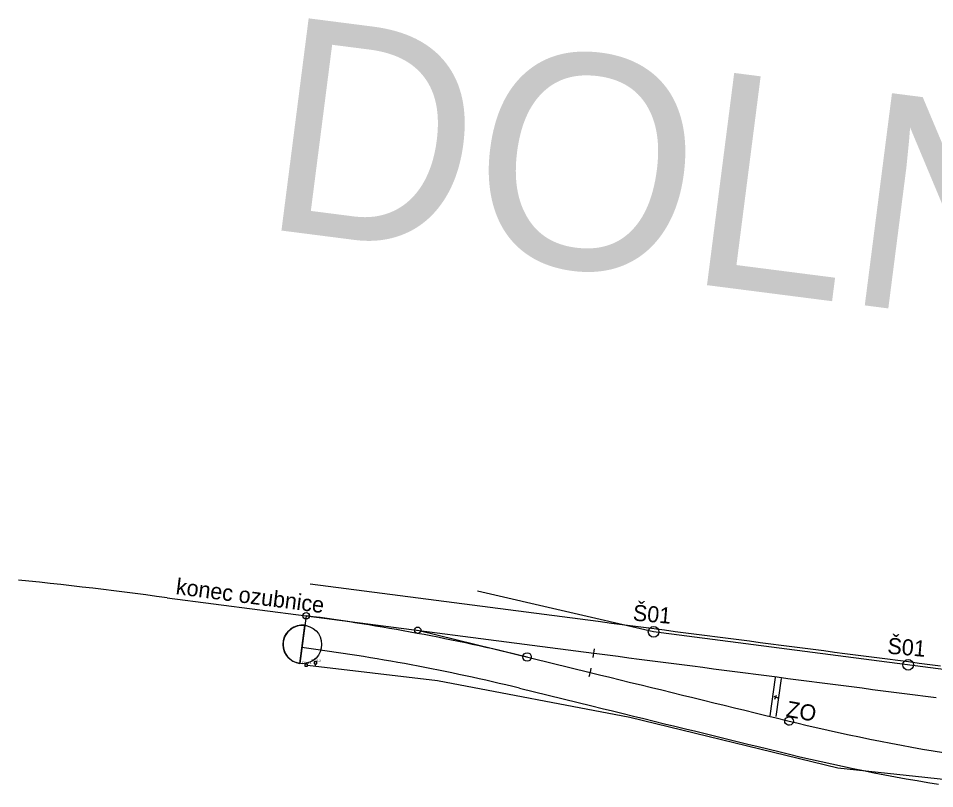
# Model space of a CAD drawing. Extents: x -669661 to -669105, y -977202 to -977030.
# Drawn here: x -669181.271 to -669176.987, y -977097.733 to -977094.133 of the extents above; entities that cross this region are included whole.
import ezdxf

# ---------------------------------------------------------------- set-up
doc = ezdxf.new("R2010")
doc.units = 0
doc.layers.add('KOL_námezníky', color=7, linetype='Continuous')
doc.layers.add('Schéma', color=7, linetype='Continuous')

# ---------------------------------------------------------------- blocks, each defined once
blk = doc.blocks.new('Z3.50')
at = {"layer": 'KOL_námezníky'}
for p, q in [((-27.7, 181.3), (-26.5, -174.8)), ((33.2, -174.7), (31.9, 181.4))]:
    blk.add_line(p, q, dxfattribs=at)

msp = doc.modelspace()

# ---------------------------------------------------------------- linework, layer by layer
at = {"layer": 'Schéma'}
for p, q in [((-669179.9065, -977096.7765), (-669178.5609, -977096.9512)), ((-669180.5762, -977096.8408), (-669179.9259, -977096.9252)), ((-669179.9259, -977096.9252), (-669179.9548, -977097.1484)), ((-669179.9259, -977096.9252), (-669178.5802, -977097.1)), ((-669179.4041, -977096.993), (-669178.5971, -977097.1903)), ((-669178.5802, -977097.1), (-669178.5664, -977097.1018)), ((-669178.5664, -977097.1018), (-669178.5168, -977097.1082)), ((-669178.5168, -977097.1082), (-669178.4672, -977097.1146)), ((-669179.9319, -977097.1512), (-669179.9324, -977097.1603)), ((-669179.9194, -977097.1519), (-669179.9319, -977097.1512)), ((-669179.9199, -977097.161), (-669179.9194, -977097.1519)), ((-669179.9198, -977097.1561), (-669179.3122, -977097.2285)), ((-669179.8883, -977097.1402), (-669179.8888, -977097.1493)), ((-669179.8888, -977097.1493), (-669179.8763, -977097.15)), ((-669179.8758, -977097.1408), (-669179.8883, -977097.1402)), ((-669179.8827, -977097.1498), (-669179.8842, -977097.1595)), ((-669179.8763, -977097.15), (-669179.8758, -977097.1408)), ((-669178.4672, -977097.1146), (-669178.4176, -977097.1211)), ((-669178.4176, -977097.1211), (-669178.368, -977097.1275)), ((-669178.368, -977097.1275), (-669178.3185, -977097.134)), ((-669178.3185, -977097.134), (-669178.2689, -977097.1404)), ((-669178.2689, -977097.1404), (-669178.2193, -977097.1468)), ((-669178.2193, -977097.1468), (-669178.1697, -977097.1533)), ((-669178.1697, -977097.1533), (-669178.1201, -977097.1597)), ((-669179.9324, -977097.1603), (-669179.9199, -977097.161)), ((-669178.5971, -977097.1903), (-669178.5542, -977097.2008)), ((-669178.1201, -977097.1597), (-669178.0705, -977097.1661)), ((-669178.0705, -977097.1661), (-669178.021, -977097.1726)), ((-669178.021, -977097.1726), (-669177.9714, -977097.179)), ((-669177.9714, -977097.179), (-669177.9218, -977097.1855)), ((-669177.9218, -977097.1855), (-669177.8722, -977097.1919)), ((-669177.8722, -977097.1919), (-669177.8226, -977097.1983)), ((-669177.8226, -977097.1983), (-669177.773, -977097.2048)), ((-669179.3122, -977097.2285), (-669178.4119, -977097.3996)), ((-669178.5542, -977097.2008), (-669178.5056, -977097.2126)), ((-669178.5056, -977097.2126), (-669178.4571, -977097.2245)), ((-669178.4571, -977097.2245), (-669178.4085, -977097.2364)), ((-669178.4085, -977097.2364), (-669178.3599, -977097.2483)), ((-669177.773, -977097.2048), (-669177.7235, -977097.2112)), ((-669177.7235, -977097.2112), (-669177.6739, -977097.2177)), ((-669177.6739, -977097.2177), (-669177.6243, -977097.2241)), ((-669177.6243, -977097.2241), (-669177.5747, -977097.2305)), ((-669177.5747, -977097.2305), (-669177.5251, -977097.237)), ((-669177.5251, -977097.237), (-669177.4755, -977097.2434)), ((-669178.9286, -977097.2636), (-669178.5898, -977097.3465)), ((-669178.3599, -977097.2483), (-669178.3114, -977097.2601)), ((-669178.3114, -977097.2601), (-669178.2628, -977097.272)), ((-669178.2628, -977097.272), (-669178.2142, -977097.2839)), ((-669178.2142, -977097.2839), (-669178.1656, -977097.2958)), ((-669177.4755, -977097.2434), (-669177.4259, -977097.2498)), ((-669177.4259, -977097.2498), (-669177.3764, -977097.2563)), ((-669177.3764, -977097.2563), (-669177.3268, -977097.2627)), ((-669177.3268, -977097.2627), (-669177.2772, -977097.2692)), ((-669177.2772, -977097.2692), (-669177.2276, -977097.2756)), ((-669177.2276, -977097.2756), (-669177.178, -977097.282)), ((-669177.178, -977097.282), (-669177.1284, -977097.2885)), ((-669178.1656, -977097.2958), (-669178.1171, -977097.3076)), ((-669178.1171, -977097.3076), (-669178.0685, -977097.3195)), ((-669178.0685, -977097.3195), (-669178.0199, -977097.3314)), ((-669177.7395, -977097.3016), (-669177.7209, -977097.3091)), ((-669177.734, -977097.3147), (-669177.7266, -977097.296)), ((-669177.1284, -977097.2885), (-669177.0789, -977097.2949)), ((-669177.0789, -977097.2949), (-669177.0293, -977097.3014)), ((-669177.0293, -977097.3014), (-669176.9797, -977097.3078)), ((-669178.5898, -977097.3465), (-669178.5413, -977097.3584)), ((-669178.5413, -977097.3584), (-669178.4927, -977097.3702)), ((-669178.4927, -977097.3702), (-669178.4441, -977097.3821)), ((-669178.0199, -977097.3314), (-669177.9714, -977097.3433)), ((-669177.9714, -977097.3433), (-669177.9228, -977097.3551)), ((-669177.9228, -977097.3551), (-669177.8742, -977097.367)), ((-669177.8742, -977097.367), (-669177.8257, -977097.3789)), ((-669178.4441, -977097.3821), (-669178.3955, -977097.394)), ((-669178.4119, -977097.3996), (-669177.4407, -977097.6364)), ((-669178.3955, -977097.394), (-669178.347, -977097.4059)), ((-669178.347, -977097.4059), (-669178.2498, -977097.4296)), ((-669177.8257, -977097.3789), (-669177.7771, -977097.3908)), ((-669177.7771, -977097.3908), (-669177.7285, -977097.4026)), ((-669177.7285, -977097.4026), (-669177.6799, -977097.4145)), ((-669178.2498, -977097.4296), (-669178.2013, -977097.4415)), ((-669178.2013, -977097.4415), (-669178.1527, -977097.4534)), ((-669178.1527, -977097.4534), (-669178.1041, -977097.4652)), ((-669177.6799, -977097.4145), (-669177.6677, -977097.4175)), ((-669177.6677, -977097.4175), (-669177.6314, -977097.4263)), ((-669177.6314, -977097.4263), (-669177.5827, -977097.4379)), ((-669177.5827, -977097.4379), (-669177.534, -977097.4492)), ((-669177.534, -977097.4492), (-669177.4852, -977097.4602)), ((-669178.1041, -977097.4652), (-669177.8613, -977097.5246)), ((-669177.4852, -977097.4602), (-669177.4364, -977097.471)), ((-669177.4364, -977097.471), (-669177.3875, -977097.4815)), ((-669177.3875, -977097.4815), (-669177.3386, -977097.4918)), ((-669177.3386, -977097.4918), (-669177.2896, -977097.5018)), ((-669177.8613, -977097.5246), (-669177.8127, -977097.5365)), ((-669177.8127, -977097.5365), (-669177.7156, -977097.5602)), ((-669177.2896, -977097.5018), (-669177.2406, -977097.5116)), ((-669177.2406, -977097.5116), (-669177.1915, -977097.5211)), ((-669177.1915, -977097.5211), (-669177.1424, -977097.5303)), ((-669177.1424, -977097.5303), (-669177.0932, -977097.5393)), ((-669177.0932, -977097.5393), (-669177.0439, -977097.548)), ((-669177.7156, -977097.5602), (-669177.7032, -977097.5632)), ((-669177.7032, -977097.5632), (-669177.6664, -977097.5722)), ((-669177.6664, -977097.5722), (-669177.617, -977097.5839)), ((-669177.617, -977097.5839), (-669177.5675, -977097.5954)), ((-669177.0439, -977097.548), (-669176.9947, -977097.5565)), ((-669176.9947, -977097.5565), (-669176.9453, -977097.5647)), ((-669177.5675, -977097.5954), (-669177.518, -977097.6066)), ((-669177.518, -977097.6066), (-669177.4684, -977097.6176)), ((-669177.4684, -977097.6176), (-669177.4187, -977097.6282)), ((-669177.4407, -977097.6364), (-669176.533, -977097.7333)), ((-669177.4187, -977097.6282), (-669177.369, -977097.6387)), ((-669177.369, -977097.6387), (-669177.3193, -977097.6489)), ((-669177.3193, -977097.6489), (-669177.2695, -977097.6588)), ((-669177.2695, -977097.6588), (-669177.2196, -977097.6684)), ((-669177.2196, -977097.6684), (-669177.1697, -977097.6778)), ((-669177.1697, -977097.6778), (-669177.1197, -977097.6869)), ((-669177.1197, -977097.6869), (-669177.0697, -977097.6958)), ((-669177.0697, -977097.6958), (-669177.0197, -977097.7044)), ((-669177.0197, -977097.7044), (-669176.9695, -977097.7127))]:
    msp.add_line(p, q, dxfattribs=at)
for points in [[(-669180.5762, -977096.8408), (-669180.6258, -977096.8344), (-669180.6754, -977096.8279), (-669180.725, -977096.8216), (-669180.7746, -977096.8152), (-669180.8242, -977096.809), (-669180.8738, -977096.8028), (-669180.9234, -977096.7967), (-669180.9731, -977096.7908), (-669181.0227, -977096.785), (-669181.0724, -977096.7793), (-669181.1221, -977096.7739), (-669181.1718, -977096.7686), (-669181.2216, -977096.7636), (-669181.2713, -977096.7587)], [(-669175.4004, -977097.3767), (-669178.3011, -977097.0001), (-669179.1249, -977096.8105)], [(-669179.9548, -977097.1484), (-669179.9317, -977096.9699), (-669179.9317, -977096.9699)], [(-669178.5609, -977096.9512), (-669178.4975, -977096.9595), (-669178.4479, -977096.9659), (-669178.3983, -977096.9723), (-669178.3487, -977096.9788), (-669178.2496, -977096.9916), (-669178.2, -977096.9981), (-669178.1504, -977097.0045), (-669178.1008, -977097.011), (-669177.9521, -977097.0303), (-669177.9025, -977097.0367), (-669177.8529, -977097.0431), (-669177.8033, -977097.0496), (-669177.6546, -977097.0689), (-669177.605, -977097.0753), (-669177.5554, -977097.0818), (-669177.5058, -977097.0882), (-669177.4562, -977097.0947), (-669177.4066, -977097.1011), (-669177.357, -977097.1075), (-669177.3075, -977097.114), (-669177.2579, -977097.1204), (-669177.2083, -977097.1268), (-669177.1587, -977097.1333), (-669177.1091, -977097.1397), (-669177.0595, -977097.1462), (-669176.9604, -977097.159)], [(-669177.6725, -977097.4369), (-669177.6786, -977097.4341), (-669177.6842, -977097.4286), (-669177.6871, -977097.4237), (-669177.6881, -977097.4166), (-669177.6862, -977097.4089), (-669177.6824, -977097.4043), (-669177.6772, -977097.4001), (-669177.6698, -977097.3978), (-669177.663, -977097.3981), (-669177.6568, -977097.401), (-669177.6513, -977097.4064), (-669177.6484, -977097.4113), (-669177.6474, -977097.4184), (-669177.6493, -977097.4261), (-669177.6531, -977097.4307), (-669177.6583, -977097.4349), (-669177.6657, -977097.4372), (-669177.6725, -977097.4369)]]:
    msp.add_lwpolyline(points, dxfattribs=at)
for centre, radius in [((-669179.9259, -977096.9252), 0.015), ((-669179.9432, -977097.0591), 0.09), ((-669179.4041, -977096.993), 0.015), ((-669178.3011, -977097.0001), 0.025), ((-669178.893, -977097.1179), 0.02), ((-669177.1111, -977097.1546), 0.025)]:
    msp.add_circle(centre, radius, dxfattribs=at)
for centre, radius, start, end in [((-669181.1491, -977106.3462), 9.5, 76.2617, 82.60174), ((-669179.9432, -977097.0591), 0.09, 82.6032, 262.6017), ((-669181.1491, -977106.3462), 9.35, 76.26134, 82.60174), ((-669179.4041, -977096.993), 0.8308, 351.2224, 353.9811), ((-669179.4041, -977096.993), 0.8308, 344.8822, 347.6409)]:
    msp.add_arc(centre, radius, start, end, dxfattribs=at)

# ---------------------------------------------------------------- block references
at = {"layer": 'Schéma', "xscale": 0.0005052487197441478, "yscale": 0.0005052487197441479, "rotation": -8.028577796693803}
msp.add_blockref('Z3.50', (-669177.7318, -977097.3066), dxfattribs=at)

# ---------------------------------------------------------------- texts
at = {"layer": 'Schéma'}
for s, height, rotation, p in [('DOLNÍ POLUBNÝ', 1, 352.6919, (-669180.15, -977095.1109)), ('konec ozubnice', 0.075, 352.6118, (-669180.5377, -977096.8236)), ('Š01', 0.075, 354.9976, (-669178.4003, -977096.9474)), ('Š01', 0.075, 354.9976, (-669177.2103, -977097.1019)), ('EOV1.1', 0.009, 357.0527, (-669179.9447, -977097.1486)), ('EOV1.2', 0.009, 357.0527, (-669179.9011, -977097.1376)), ('ZO', 0.075, 349.8596, (-669177.6853, -977097.396))]:
    msp.add_text(s, height=height, rotation=rotation, dxfattribs=at).set_placement(p)

doc.saveas('drawing.dxf')
